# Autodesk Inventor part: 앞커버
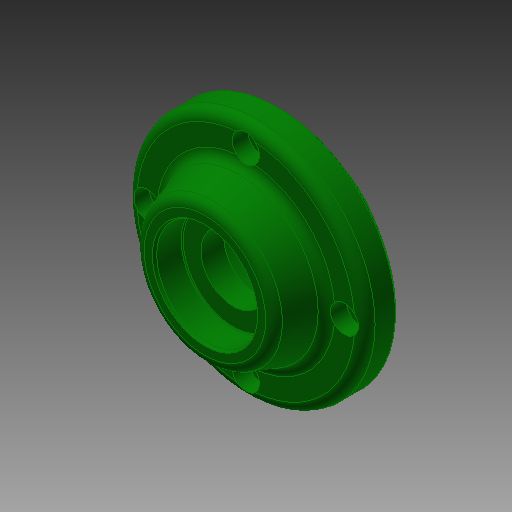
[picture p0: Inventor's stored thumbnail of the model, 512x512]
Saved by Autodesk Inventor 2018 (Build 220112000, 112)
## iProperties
Created: 2017-08
Part Number: 앞커버
Material: 알루미늄 6061
Document SubType Name: Modeling
Designer: mduedu
Density: 1 g/cm^3
Appearance: 진녹색
Author: mduedu
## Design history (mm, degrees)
sketch "스케치1"
  geometry: C1 r 35 at (0, 0); 1 further point
  constraints: 1 centre point, 1 coincident
  dimensions: "d0" = 70 diameter of C1
extrude "돌출1" new body sketch "스케치1" distance "d1" = 10; taper "d2" = 0 deg
sketch "스케치2"
  geometry: C1 r 24 at (0, 0); 1 further point
  constraints: 1 centre point, 1 coincident
  dimensions: "d3" = 48 diameter of C1
node "작업 평면1"
sketch "스케치3"
  geometry: C1 r 20 at (0, 0); 1 further point
  constraints: 1 centre point, 1 coincident
  dimensions: "d5" = 40 diameter of C1
feature "로프트1" sketch "스케치3" dims "d6" = 0, "d7" = 90 deg, "d8" = 0, "d9" = 90 deg
sketch "스케치4"
  geometry: C1 r 24 at (0, 0) reference; 1 further point
extrude "돌출2" join sketch "스케치4" distance "d10" = 8; taper "d11" = 0 deg
hole "구멍1" diameter "d14" = 40; stored, may be unused: countersink angle "d18" = 90 deg, drill point angle "d20" = 0 deg; dims "d12" = 10, "d13" = 10, "d15" = 6, "d16" = 4, "d17" = 2, "d19" = 12
hole "구멍2" diameter "d23" = 34; stored, may be unused: countersink angle "d27" = 90 deg, drill point angle "d29" = 0 deg; dims "d21" = 10, "d22" = 10, "d24" = 6, "d25" = 4, "d26" = 2, "d28" = 3
hole "구멍3" diameter "d32" = 19; stored, may be unused: countersink angle "d36" = 90 deg, drill point angle "d38" = 0 deg; dims "d30" = 10, "d31" = 10, "d33" = 6, "d34" = 4, "d35" = 2, "d37" = 3
chamfer "모따기1" distance "d39" = 1; stored, may be unused: second distance "d40" = 2, angle "d41" = 45 deg
sketch "스케치5"
  geometry: C1 r 15 at (0, 0); 1 further point
  constraints: 1 centre point, 1 coincident
  dimensions: "d42" = 30 diameter of C1
extrude "돌출3" cut sketch "스케치5" distance "d43" = 8.3; taper "d44" = 0 deg
chamfer "모따기2" distance "d47" = 0.8; stored, may be unused: second distance "d48" = 2, angle "d49" = 30 deg
fillet "모깎기1" dims "d50" = 0.3
fillet "모깎기2" dims "d51" = 0.3
fillet "모깎기3" dims "d52" = 3
sketch "스케치6" dims "d53" = 58
  geometry: 6 further points
  constraints: 2 vertical alignment, 1 coincident, 7 other
  dimensions: "d56" = 360 deg dimension on point (0, 0) point (0, 29) (derived)
sketch "스케치9"
  geometry: 4 further points
  constraints: 4 other
hole "구멍6" sketch "스케치9" at (-29, 0), (0, -29), (29, 0), (0, 29) diameter "d72" = 4.5; stored, may be unused: countersink angle "d76" = 90 deg, drill point angle "d78" = 0 deg; dims "d73" = 6, "d74" = 8, "d75" = 4.6, "d77" = 8
fillet "모깎기4" dims "d79" = 3
fillet "모깎기5" dims "d80" = 3
fillet "모깎기6" dims "d81" = 3
chamfer "모따기3" distance "d82" = 1; stored, may be unused: second distance "d83" = 2, angle "d84" = 30 deg
node "솔리드1"
other parameters: "d4" = 12
